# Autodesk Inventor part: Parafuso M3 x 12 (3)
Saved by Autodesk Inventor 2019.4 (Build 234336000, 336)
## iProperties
Created: 2020-03
Part Number: Parafuso M3 x 12 (3)
Material: Generic
Document SubType Name: Modeling
Designer: Administrator
Density: 1 g/cm^3
Appearance: Default
Title: Parafuso M3 x 12 (3)
Author: Administrator
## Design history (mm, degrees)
feature "Parafuso M3 x 12 (3)"
body "Solid1"
